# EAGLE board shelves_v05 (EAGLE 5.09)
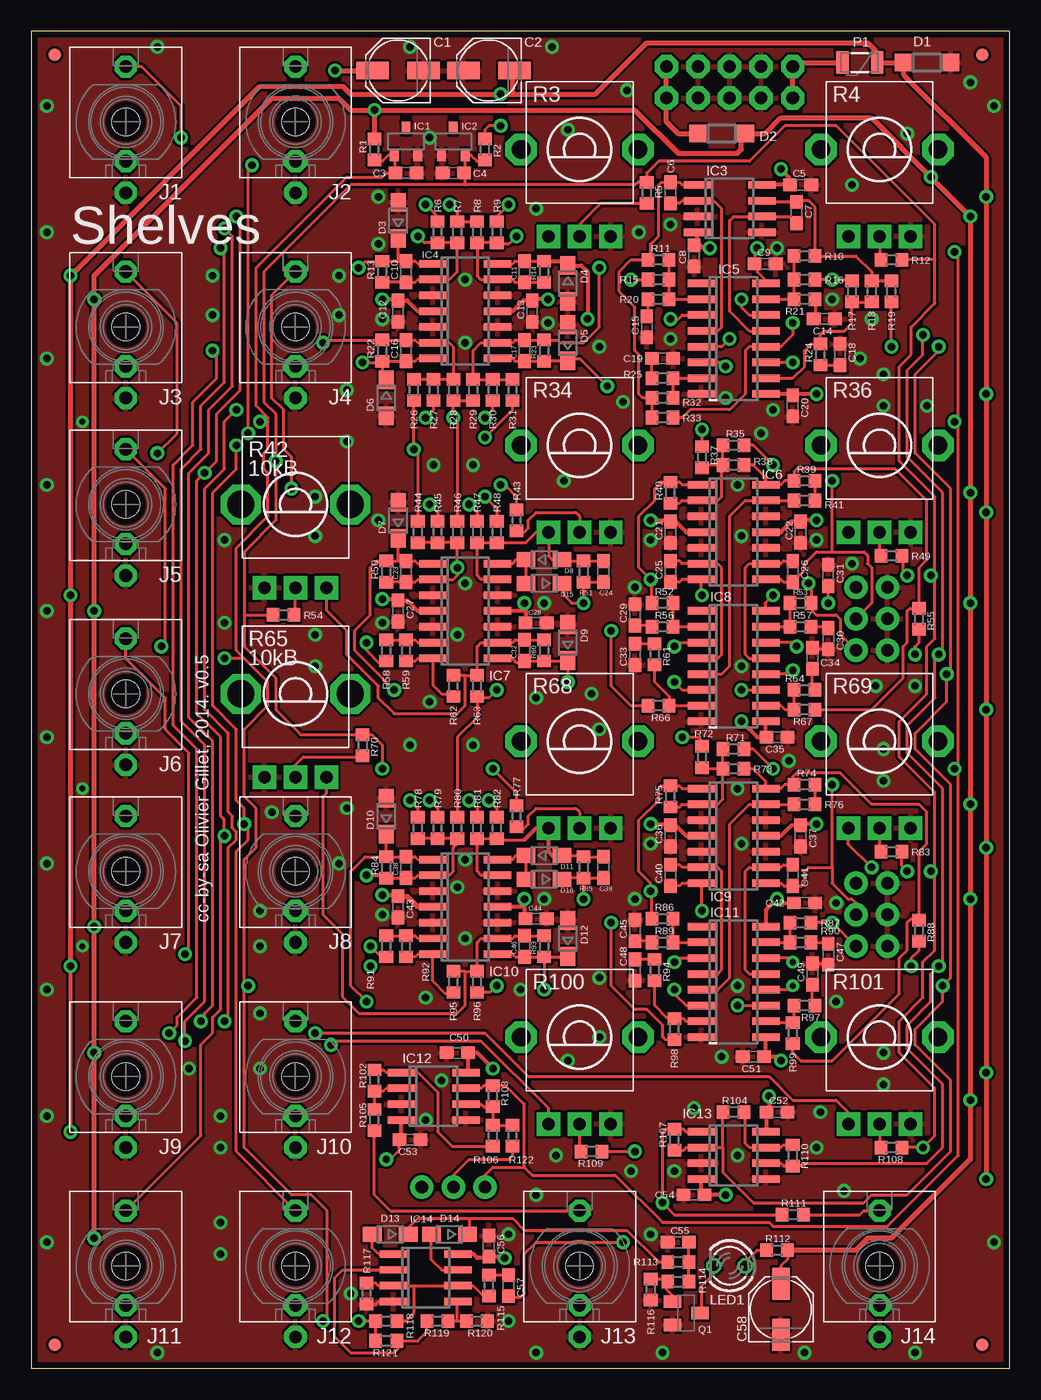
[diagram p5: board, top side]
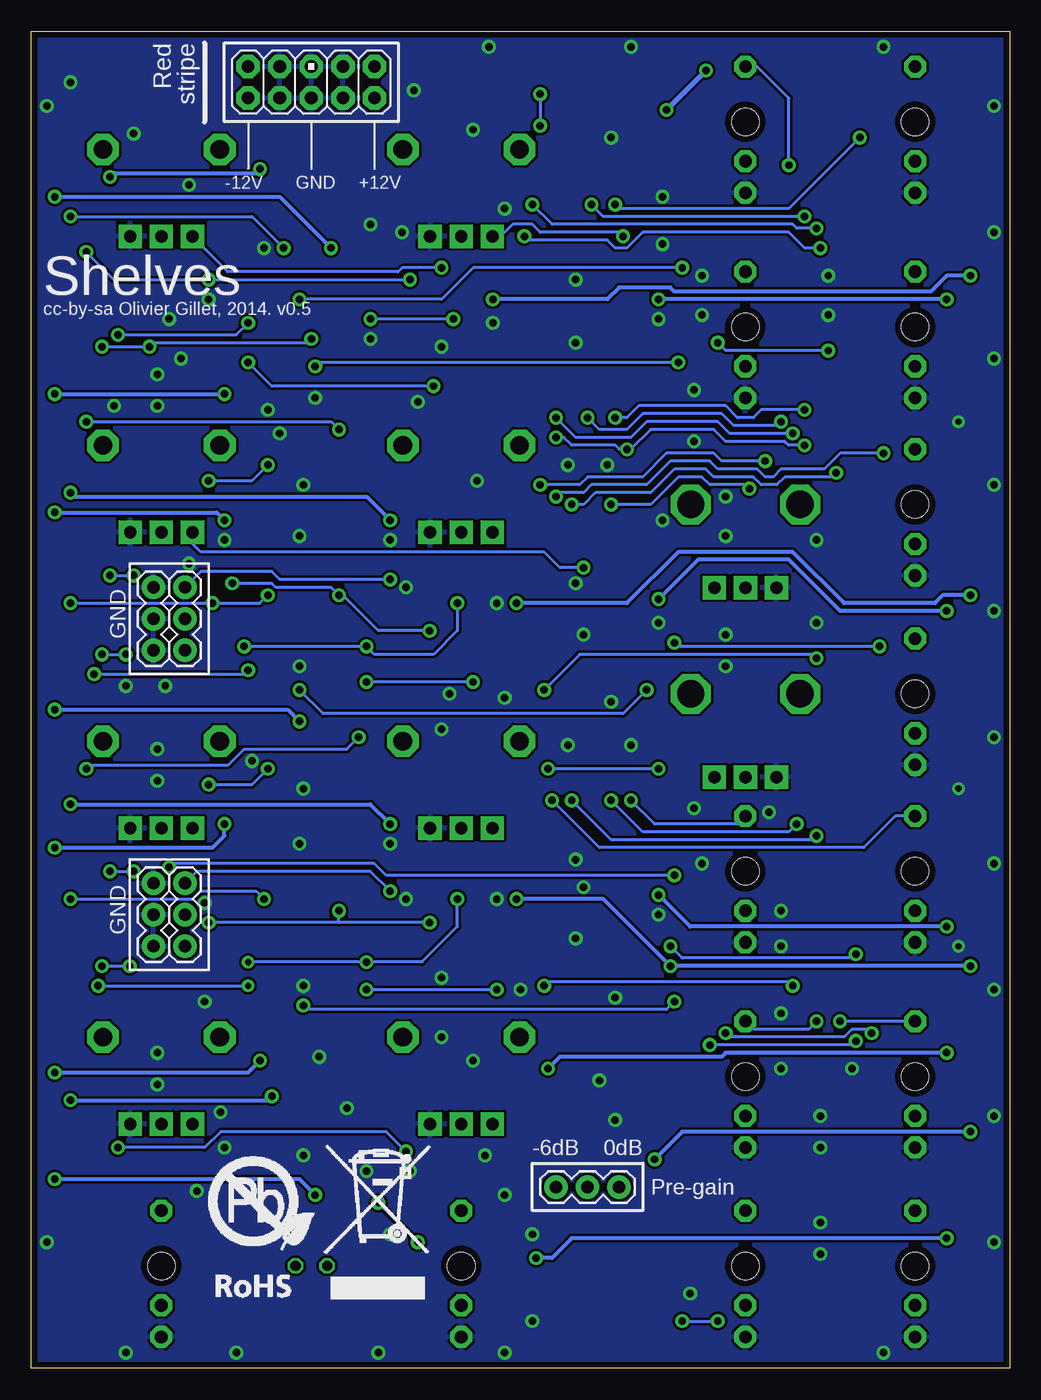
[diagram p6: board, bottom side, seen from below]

Size 78.74 x 107.63 mm. Coordinates in mm from the lower left corner, seen from the top.
Outline: 0,0 78.74,0 78.74,107.63 0,107.63 0,0
Copper layers (1*16): Top 0.035mm / dielectric 1.5mm / Bottom 0.035mm
Design rules "PCBCart-Standard": minimum track width 8mil, minimum drill 0.4mm, track to track 8mil, track to pad 8mil, pad to pad 8mil, via to via 8mil, smd to smd 8mil, copper to edge 20mil, drill to drill 8mil, minimum pad ring 8mil, minimum via ring 10mil, stop-mask expansion 3mil, vias tented up to drill 25mil, thermal gap 8mil

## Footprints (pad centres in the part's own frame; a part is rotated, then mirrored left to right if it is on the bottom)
PANASONIC_C = smd 2.6 x 1.4: + 2.05,0; - -2.05,0
C0603 = smd 1.1 x 1: 1 -0.85,0; 2 0.85,0
SOD123 = smd 1.4 x 1.4: A 1.9,0; C -1.9,0
SOD323-W = smd 1.5 x 1.2: A 1.45,0; C -1.45,0
DBZ_R-PDSO-G3 = smd 0.7 x 1: 1 -0.95,-1.1; 2 0.95,-1.1; 3 0,1.1
SO08 = smd 0.6 x 2.2: 1 -1.905,-2.6; 2 -0.635,-2.6; 3 0.635,-2.6; 4 1.905,-2.6; 5 1.905,2.6; 6 0.635,2.6; 7 -0.635,2.6; 8 -1.905,2.6
SO14 = smd 0.6 x 2.2: 1 -3.81,-2.6; 2 -2.54,-2.6; 3 -1.27,-2.6; 4 0,-2.6; 5 1.27,-2.6; 6 2.54,-2.6; 7 3.81,-2.6; 8 3.81,2.6; 9 2.54,2.6; 10 1.27,2.6; 11 0,2.6; 12 -1.27,2.6; 13 -2.54,2.6; 14 -3.81,2.6
SOIC16N = smd 0.6 x 2.2: 1 -4.445,-2.6; 2 -3.175,-2.6; 3 -1.905,-2.6; 4 -0.635,-2.6; 5 0.635,-2.6; 6 1.905,-2.6; 7 3.175,-2.6; 8 4.445,-2.6; 9 4.445,2.6; 10 3.175,2.6; 11 1.905,2.6; 12 0.635,2.6; 13 -0.635,2.6; 14 -1.905,2.6; 15 -3.175,2.6; 16 -4.445,2.6
WQP_PJ_301M6 = drill 1.016 pad 1.778 octagon: P1 0,-5.715; P2 0,-3.175; P3 0,4.445 | hole 2.2: 0,0
FIDUCIAL-1X2 = smd 1 x 1: 1 0,0
1X03 = drill 1.016 pad 1.88 round: 1 0,0; 2 2.54,0; 3 5.08,0
AVR_ICSP = drill 1.016 pad 1.88 octagon: 1 -1.27,5.08; 2 1.27,5.08; 3 -1.27,2.54; 4 1.27,2.54; 5 -1.27,0; 6 1.27,0; 7 -1.27,-2.54; 8 1.27,-2.54; 9 -1.27,-5.08; 10 1.27,-5.08
LED3MM = drill 0.813 octagon: A -1.27,0; K 1.27,0
PTC-1206 = smd 1 x 1.8: 1 -1.4,0; 2 1.4,0
SOT23-BEC = smd 1 x 1.4: B -0.95,-1.1; C 0,1.1; E 0.95,-1.1
R0603 = smd 1 x 1.1: 1 -0.85,0; 2 0.85,0
ALPS_POT_VERTICAL_PS = drill 1 pad 1.88 square: P$1 -2.5,7; P$2 0,7; P$3 2.5,7 | drill 1.5 pad 2.54 octagon: P$4 -4.7,0; P$5 4.7,0
ALPS_POT_VERTICAL = drill 1 pad 1.88 square: P$1 -2.5,6.7; P$2 0,6.7; P$3 2.5,6.7 | drill 2.2 pad 3.175 octagon: P$4 -4.4,0; P$5 4.4,0

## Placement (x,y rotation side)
C1  22u  [PANASONIC_C]  29.53,104.46 180 top
C2  22u  [PANASONIC_C]  36.83,104.46 180 top
C3  100n  [C0603]  30.16,96.2 0 top
C4  100n  [C0603]  33.97,96.2 180 top
C5  100n  [C0603]  61.91,95.25 0 top
C6  68p  [C0603]  51.44,94.61 90 top
C7  68p  [C0603]  61.59,93.03 90 top
C8  100n  [C0603]  53.34,89.53 90 top
C9  100n  [C0603]  59.05,88.9 0 top
C10  560p  [C0603]  30.16,88.27 270 top
C11  560p  [C0603]  39.69,88.27 270 top
C12  100n  [C0603]  29.53,85.09 270 top
C13  100n  [C0603]  40.32,85.09 90 top
C14  560p  [C0603]  63.82,84.45 0 top
C15  560p  [C0603]  49.53,83.82 270 top
C16  560p  [C0603]  30.16,81.92 90 top
C17  560p  [C0603]  39.69,81.92 90 top
C18  560p  [C0603]  65.09,81.6 90 top
C19  560p  [C0603]  50.8,81.28 0 top
C20  100n  [C0603]  61.28,77.47 90 top
C21  100n  [C0603]  51.44,67.31 270 top
C22  100n  [C0603]  61.91,67.31 90 top
C23  560p  [C0603]  30.16,64.14 270 top
C24  560p  [C0603]  46.04,64.14 90 top
C25  68p  [C0603]  51.44,64.14 270 top
C26  68p  [C0603]  61.28,64.14 270 top
C27  100n  [C0603]  29.53,60.96 270 top
C28  100n  [C0603]  40.64,60.01 180 top
C29  560p  [C0603]  48.58,60.64 90 top
C30  560p  [C0603]  64.14,58.74 270 top
C31  100n  [C0603]  64.14,63.82 90 top
C32  560p  [C0603]  39.69,57.78 90 top
C33  560p  [C0603]  48.58,57.47 270 top
C34  560p  [C0603]  62.87,57.15 90 top
C35  100n  [C0603]  60.01,50.8 180 top
C36  100n  [C0603]  51.44,42.86 270 top
C37  100n  [C0603]  61.91,42.86 90 top
C38  560p  [C0603]  30.16,40.32 270 top
C39  560p  [C0603]  46.04,40.32 90 top
C40  68p  [C0603]  51.44,39.69 270 top
C41  68p  [C0603]  61.28,39.69 270 top
C42  100n  [C0603]  62.23,37.47 0 top
C43  100n  [C0603]  29.53,37.15 270 top
C44  100n  [C0603]  40.64,36.2 180 top
C45  560p  [C0603]  48.58,35.24 90 top
C46  560p  [C0603]  39.69,33.97 90 top
C47  560p  [C0603]  64.14,33.34 270 top
C48  560p  [C0603]  48.58,32.07 270 top
C49  560p  [C0603]  62.87,31.75 90 top
C50  100n  [C0603]  34.29,25.4 180 top
C51  100n  [C0603]  58.1,25.08 0 top
C52  100n  [C0603]  60.01,20.64 0 top
C53  100n  [C0603]  30.48,18.41 180 top
C54  100n  [C0603]  53.34,13.97 0 top
C55  100n  [C0603]  52.07,10.16 180 top
C56  100n  [C0603]  36.83,9.84 90 top
C57  100n  [C0603]  38.42,6.67 270 top
C58  22u  [PANASONIC_C]  60.33,4.76 90 top
D1  1N5819HW  [SOD123]  72.07,105.09 180 top
D2  1N5819HW  [SOD123]  55.56,99.38 180 top
D3  1N4148  [SOD323-W]  29.53,92.39 90 top
D4  1N4148  [SOD323-W]  43.18,87.31 270 top
D5  1N4148  [SOD323-W]  43.18,82.55 90 top
D6  1N4148  [SOD323-W]  28.57,78.11 270 top
D7  1N4148  [SOD323-W]  29.53,68.26 90 top
D8  1N4148  [SOD323-W]  41.27,65.09 0 top
D9  1N4148  [SOD323-W]  43.18,58.42 90 top
D10  1N4148  [SOD323-W]  28.57,44.45 90 top
D11  1N4148  [SOD323-W]  41.27,41.27 0 top
D12  1N4148  [SOD323-W]  43.18,34.61 90 top
D13  1N4148  [SOD323-W]  28.89,10.79 180 top
D14  1N4148  [SOD323-W]  33.66,10.79 180 top
D15  1N4148  [SOD323-W]  41.27,63.18 180 top
D16  1N4148  [SOD323-W]  41.27,39.37 180 top
IC1  LM4040B10  [DBZ_R-PDSO-G3]  30.16,98.74 0 top
IC2  LM4040B10  [DBZ_R-PDSO-G3]  33.97,98.74 0 top
IC3  TL072D  [SO08]  56.2,93.34 270 top
IC4  TL074D  [SO14]  34.92,85.09 270 top
IC5  V2164SZ  [SOIC16N]  56.52,82.87 270 top
IC6  TL074D  [SO14]  56.52,67.31 270 top
IC7  TL074D  [SO14]  34.92,60.96 270 top
IC8  V2164SZ  [SOIC16N]  56.52,56.52 270 top
IC9  TL074D  [SO14]  56.52,42.86 270 top
IC10  TL074D  [SO14]  34.92,37.15 270 top
IC11  V2164SZ  [SOIC16N]  56.52,31.11 270 top
IC12  TL072D  [SO08]  32.38,21.91 270 top
IC13  TL072D  [SO08]  56.52,17.14 270 top
IC14  TL072D  [SO08]  31.75,7.3 270 top
J1  PJ301_THONKICONN6  [WQP_PJ_301M6]  7.62,100.33 0 top
J2  PJ301_THONKICONN6  [WQP_PJ_301M6]  21.27,100.33 0 top
J3  PJ301_THONKICONN6  [WQP_PJ_301M6]  7.62,83.82 0 top
J4  PJ301_THONKICONN6  [WQP_PJ_301M6]  21.27,83.82 0 top
J5  PJ301_THONKICONN6  [WQP_PJ_301M6]  7.62,69.53 0 top
J6  PJ301_THONKICONN6  [WQP_PJ_301M6]  7.62,54.29 0 top
J7  PJ301_THONKICONN6  [WQP_PJ_301M6]  7.62,40.01 0 top
J8  PJ301_THONKICONN6  [WQP_PJ_301M6]  21.27,40.01 0 top
J9  PJ301_THONKICONN6  [WQP_PJ_301M6]  7.62,23.5 0 top
J10  PJ301_THONKICONN6  [WQP_PJ_301M6]  21.27,23.5 0 top
J11  PJ301_THONKICONN6  [WQP_PJ_301M6]  7.62,8.26 0 top
J12  PJ301_THONKICONN6  [WQP_PJ_301M6]  21.27,8.26 0 top
J13  PJ301_THONKICONN6  [WQP_PJ_301M6]  44.13,8.26 0 top
J14  PJ301_THONKICONN6  [WQP_PJ_301M6]  68.26,8.26 0 top
JP1  FIDUCIAL1X2  [FIDUCIAL-1X2]  1.91,105.73 0 top
JP2  FIDUCIAL1X2  [FIDUCIAL-1X2]  76.52,105.73 0 top
JP3  FIDUCIAL1X2  [FIDUCIAL-1X2]  1.91,1.91 0 top
JP4  FIDUCIAL1X2  [FIDUCIAL-1X2]  76.52,1.91 0 top
JP5  [1X03]  66.36,57.78 90 bottom
JP6  [1X03]  68.9,57.78 90 bottom
JP7  [1X03]  68.9,33.97 90 bottom
JP11  M05X2PTH  [AVR_ICSP]  56.2,103.5 270 bottom
JP12  [1X03]  31.43,14.61 180 bottom
JP13  [1X03]  66.36,33.97 90 bottom
LED1  WP-710A10GD  [LED3MM]  56.2,8.26 180 top
P1  PTCSMD  [PTC-1206]  66.67,105.09 180 top
Q1  MMBT3904  [SOT23-BEC]  52.7,4.45 270 top
R1  3.3k  [R0603]  27.62,98.11 270 top
R2  1.0k  [R0603]  36.51,98.11 270 top
R3  10kB  [ALPS_POT_VERTICAL_PS]  44.13,98.11 180 top
R4  10kB  [ALPS_POT_VERTICAL_PS]  68.26,98.11 180 top
R5  100k  [R0603]  49.53,94.61 270 top
R6  100k  [R0603]  32.7,91.44 270 top
R7  100k  [R0603]  34.29,91.44 270 top
R8  100k  [R0603]  35.88,91.44 270 top
R9  100k  [R0603]  37.47,91.44 270 top
R10  100k  [R0603]  62.23,89.53 0 top
R11  100k  [R0603]  50.48,89.22 180 top
R12  100k  [R0603]  69.22,89.22 180 top
R13  18k  [R0603]  28.26,88.27 90 top
R14  18k  [R0603]  41.27,88.27 90 top
R15  100k  [R0603]  50.48,87.63 0 top
R16  100k  [R0603]  62.23,87.63 180 top
R17  100k  [R0603]  66.04,86.68 270 top
R18  100k  [R0603]  67.63,86.68 270 top
R19  100k  [R0603]  69.22,86.68 270 top
R20  510  [R0603]  50.48,86.04 0 top
R21  510  [R0603]  62.23,86.04 180 top
R22  12k  [R0603]  28.26,81.92 270 top
R23  12k  [R0603]  41.27,81.92 270 top
R24  510  [R0603]  63.5,81.6 90 top
R25  510  [R0603]  50.8,79.69 0 top
R26  120k  [R0603]  30.8,78.74 90 top
R27  120k  [R0603]  32.38,78.74 90 top
R28  200k  [R0603]  33.97,78.74 90 top
R29  200k  [R0603]  35.56,78.74 90 top
R30  120k  [R0603]  37.15,78.74 90 top
R31  120k  [R0603]  38.73,78.74 90 top
R32  100k  [R0603]  50.8,78.11 0 top
R33  100k  [R0603]  50.8,76.52 0 top
R34  10kB  [ALPS_POT_VERTICAL_PS]  44.13,74.3 180 top
R35  100k  [R0603]  56.52,74.3 0 top
R36  10kB  [ALPS_POT_VERTICAL_PS]  68.26,74.3 180 top
R37  100k  [R0603]  53.98,73.34 270 top
R38  100k  [R0603]  56.52,72.71 0 top
R39  100k  [R0603]  62.23,71.44 0 top
R40  100k  [R0603]  51.44,70.48 90 top
R41  100k  [R0603]  62.23,69.85 180 top
R42  10kB  [ALPS_POT_VERTICAL]  21.27,69.53 180 top
R43  100k  [R0603]  39.05,68.26 270 top
R44  120k  [R0603]  31.11,67.31 270 top
R45  120k  [R0603]  32.7,67.31 270 top
R46  200k  [R0603]  34.29,67.31 270 top
R47  100k  [R0603]  35.88,67.31 270 top
R48  100k  [R0603]  37.47,67.31 270 top
R49  100k  [R0603]  69.22,65.41 180 top
R50  12k  [R0603]  28.57,64.14 90 top
R51  18k  [R0603]  44.45,64.14 270 top
R52  100k  [R0603]  50.8,61.59 0 top
R53  100k  [R0603]  61.91,61.59 180 top
R54  200k  [R0603]  20.32,60.64 0 top
R55  100k  [R0603]  71.44,60.33 270 top
R56  510  [R0603]  50.8,59.69 0 top
R57  510  [R0603]  61.91,59.69 180 top
R58  100k  [R0603]  28.57,57.78 90 top
R59  100k  [R0603]  30.16,57.78 270 top
R60  22k  [R0603]  41.27,57.78 270 top
R61  510  [R0603]  50.16,57.47 270 top
R62  150k  [R0603]  33.97,54.93 90 top
R63  1.5M  [R0603]  35.88,54.93 90 top
R64  510  [R0603]  62.23,54.61 180 top
R65  10kB  [ALPS_POT_VERTICAL]  21.27,54.29 180 top
R66  100k  [R0603]  50.48,53.34 0 top
R67  100k  [R0603]  62.23,53.02 180 top
R68  10kB  [ALPS_POT_VERTICAL_PS]  44.13,50.48 180 top
R69  10kB  [ALPS_POT_VERTICAL_PS]  68.26,50.48 180 top
R70  200k  [R0603]  26.67,50.16 270 top
R71  100k  [R0603]  56.52,49.85 0 top
R72  100k  [R0603]  53.98,49.21 270 top
R73  100k  [R0603]  56.52,48.26 0 top
R74  100k  [R0603]  62.23,46.99 0 top
R75  100k  [R0603]  51.44,46.04 90 top
R76  100k  [R0603]  62.23,45.4 180 top
R77  100k  [R0603]  39.05,44.45 270 top
R78  120k  [R0603]  31.11,43.5 270 top
R79  120k  [R0603]  32.7,43.5 270 top
R80  200k  [R0603]  34.29,43.5 270 top
R81  100k  [R0603]  35.88,43.5 270 top
R82  100k  [R0603]  37.47,43.5 270 top
R83  100k  [R0603]  69.22,41.59 180 top
R84  12k  [R0603]  28.57,40.32 90 top
R85  18k  [R0603]  44.45,40.32 270 top
R86  100k  [R0603]  50.8,36.2 0 top
R87  100k  [R0603]  61.91,35.88 180 top
R88  100k  [R0603]  71.44,35.24 270 top
R89  510  [R0603]  50.8,34.29 0 top
R90  510  [R0603]  61.91,34.29 180 top
R91  100k  [R0603]  28.57,33.97 90 top
R92  100k  [R0603]  30.16,33.97 270 top
R93  22k  [R0603]  41.27,33.97 270 top
R94  510  [R0603]  50.16,32.07 270 top
R95  150k  [R0603]  33.97,31.11 90 top
R96  1.5M  [R0603]  35.88,31.11 90 top
R97  510  [R0603]  62.23,29.21 180 top
R98  100k  [R0603]  51.75,27.3 90 top
R99  100k  [R0603]  61.28,26.99 90 top
R100  10kB  [ALPS_POT_VERTICAL_PS]  44.13,26.67 180 top
R101  10kB  [ALPS_POT_VERTICAL_PS]  68.26,26.67 180 top
R102  100k  [R0603]  27.62,23.18 90 top
R103  100k  [R0603]  37.15,21.91 90 top
R104  100k  [R0603]  56.52,20.64 180 top
R105  100k  [R0603]  27.62,20 90 top
R106  200k  [R0603]  37.15,18.73 90 top
R107  200k  [R0603]  51.75,18.41 90 top
R108  100k  [R0603]  69.22,17.78 180 top
R109  100k  [R0603]  45.09,17.46 180 top
R110  100k  [R0603]  61.28,17.14 90 top
R111  1.0k  [R0603]  61.28,12.38 0 top
R112  1.0k  [R0603]  60.01,9.53 0 top
R113  12k  [R0603]  52.07,8.57 0 top
R114  100k  [R0603]  52.07,6.99 180 top
R115  100k  [R0603]  36.83,6.67 270 top
R116  22k  [R0603]  49.85,6.35 90 top
R117  100k  [R0603]  26.99,6.03 90 top
R118  100k  [R0603]  28.57,3.81 180 top
R119  220k  [R0603]  32.7,3.81 180 top
R120  100k  [R0603]  35.88,3.81 180 top
R121  100k  [R0603]  28.57,2.22 180 top
R122  100k  [R0603]  38.73,18.73 270 top
U$2  [ROHS_BIG]  65.72,4.76 0 bottom

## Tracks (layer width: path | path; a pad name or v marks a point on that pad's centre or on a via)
AREF_+10  (via drill 0.6)
  Top 0.254: C3.1 29.31,97.54 IC1.1 28.75,97.64 28.26,97.16 27.73,97.16 R1.2 | C3.1 29.21,96.1 | 19.05,76.2 19.05,76.52 18.1,77.47 18.1,88.58 25.4,95.89 28.26,95.89 28.57,96.2 C3.1 | 17.14,57.15 19.05,55.24 19.05,53.34 17.14,51.44 17.14,46.04 18.1,45.09 18.1,41.91 17.14,40.96 17.14,30.8 | 17.14,57.15 16.51,57.78 16.51,66.04 19.05,68.58 19.05,72.07 18.73,72.39 18.73,73.66 19.05,73.98 19.05,76.2 | R29.1 R28.1 v33.97,76.52 34.29,76.2 R46.1 | 19.05,76.2 v18.41,76.2 | 17.14,57.15 v15.56,57.15 | R121.2 R118.2 v26.35,3.81 | v23.5,3.81 23.81,4.13 23.81,12.7 22.54,13.97 20.95,13.97 17.14,17.78 17.14,30.8 | 17.14,30.8 v17.46,30.8 | R80.1 34.29,50.8 35.88,52.39 R63.1 35.98,53.98 36.83,53.98 v37.47,54.61 | v37.47,30.8 36.93,30.27 R96.1
  Bottom 0.254: v33.97,76.52 33.02,75.56 30.8,75.56 29.53,76.83 23.18,76.83 22.23,75.88 18.73,75.88 v18.41,76.2 | v15.56,57.15 15.88,57.47 34.61,57.47 v37.47,54.61 | v26.35,3.81 v23.5,3.81 | v17.46,30.8 17.78,31.11 37.15,31.11 v37.47,30.8
AREF_-10  (via drill 0.6)
  Top 0.254: R108.1 v71.75,17.78 72.71,18.73 72.71,22.54 69.85,25.4 69.85,27.94 71.75,29.84 71.75,32.7 72.71,33.66 72.71,40.01 | 72.71,40.01 72.71,46.35 69.85,49.21 69.85,52.07 72.07,54.29 72.07,58.1 72.71,58.74 72.71,63.82 | 72.71,63.82 72.71,70.17 69.85,73.03 69.85,80.64 70.8,81.6 70.8,83.82 72.71,85.72 72.71,89.22 | 72.71,89.22 72.71,92.08 64.77,100.01 60.64,100.01 57.78,97.16 50.48,97.16 49.53,96.2 R5.1 48.79,95.47 48.58,95.25 34.92,95.25 | 72.71,89.22 R12.1 | R49.1 70.17,65.3 70.17,64.14 v70.48,63.82 | 72.71,63.82 v72.39,63.82 | 70.17,41.49 R83.1 70.06,40.42 v70.48,40.01 | 72.71,40.01 v72.39,40.01 | 17.14,60.64 17.14,58.1 19.68,55.56 19.68,53.02 21.69,51.02 R70.1 | 17.14,60.64 17.14,65.72 19.68,68.26 v19.68,73.03 19.68,76.83 18.73,77.79 18.73,88.27 25.72,95.25 34.92,95.25 | 17.14,60.64 R54.1 | R70.1 26.57,51.12 | v28.26,48.26 28.26,50.16 27.41,51.02 R70.1 | R109.1 v48.58,17.46 | R2.2 36.41,97.16 35.88,97.16 35.39,97.64 IC2.2 34.92,96.3 C4.1 34.92,96.1 34.92,95.25 | R77.1 39.05,46.35 v37.15,48.26 | v37.78,71.12 38.1,71.12 39.05,70.17 R43.1
  Bottom 0.254: v72.39,63.82 v70.48,63.82 | v72.39,40.01 v70.48,40.01 | v37.78,71.12 34.61,71.12 33.97,71.75 29.53,71.75 27.62,73.66 23.81,73.66 23.18,73.03 v19.68,73.03 | v28.26,48.26 v37.15,48.26 | v48.58,17.46 50.16,19.05 63.5,19.05 64.77,17.78 v71.75,17.78
BP_1  (via drill 0.6)
  Top 0.254: v53.98,36.83 53.98,38.99 IC9.7 52.39,39.05 52.17,38.84 C40.2 | R87.1 v64.45,35.88 JP13.1 | R98.1 51.02,26.45 50.8,26.67 50.8,27.62 49.53,28.89 48.58,28.89 46.67,30.8 v46.67,35.88
  Bottom 0.254: 53.98,35.88 v64.45,35.88 | v46.67,35.88 53.98,35.88 | 53.98,35.88 v53.98,36.83
BP_2  (via drill 0.6)
  Top 0.254: C25.2 52.17,63.28 52.39,63.5 IC6.7 53.91,62.29 v53.98,62.23 | R66.1 48.26,53.34 46.67,54.93 v46.67,59.37 | v62.55,63.18 62.76,62.97 R53.1 62.87,61.49 62.87,60.96 63.18,60.64 64.77,60.64 65.09,60.33 65.09,59.05 JP5.1
  Bottom 0.254: v46.67,59.37 50.8,59.37 53.66,62.23 v53.98,62.23 54.61,62.87 59.05,62.87 59.37,63.18 v62.55,63.18
F_GLOBAL  (via drill 0.6)
  Top 0.254: R8.1 R7.1 34.29,93.03 v33.66,93.66 | v16.51,92.71 16.83,92.39 16.83,78.74 14.92,76.83 14.92,73.03 v13.97,72.07 13.34,71.44 13.34,52.7 15.24,50.8 15.24,44.45 15.56,44.13 v15.56,42.86 15.24,42.55 15.24,28.89 14.61,28.26 14.61,26.99 13.65,26.04 13.65,18.73 J11.P3 | v35.24,69.53 35.88,68.9 R47.1 | v35.24,45.72 35.88,45.09 R81.1
  Bottom 0.254: v33.66,93.66 32.7,92.71 v16.51,92.71 | v13.97,72.07 14.29,71.75 18.1,71.75 18.73,71.12 20,71.12 20.64,71.75 23.81,71.75 24.45,72.39 26.99,72.39 28.89,70.48 33.34,70.48 34.29,69.53 v35.24,69.53 | v35.24,45.72 32.07,42.55 15.88,42.55 v15.56,42.86
GAIN_GLOBAL  (via drill 0.6)
  Top 0.254: J12.P3 16.51,17.46 16.51,41.59 17.46,42.55 17.46,43.5 v17.14,43.81 17.14,45.09 16.51,45.72 16.51,51.44 14.61,53.34 14.61,70.48 16.51,72.39 v16.51,74.3 | R31.1 38.73,77.15 v36.51,74.93 | R26.1 v30.8,73.98 31.11,73.66 R44.1 | v32.07,45.72 32.7,45.09 R79.1
  Bottom 0.254: v16.51,74.3 17.78,74.3 18.1,74.61 22.86,74.61 23.81,75.56 28.89,75.56 30.48,73.98 v30.8,73.98 31.43,73.98 31.75,74.3 35.24,74.3 35.88,74.93 v36.51,74.93 | v32.07,45.72 29.53,43.18 17.78,43.18 v17.14,43.81
GND  (via drill 0.5, 0.6)
  Top 0.254: C47.2 64.02,32.6 C49.2 | IC14.4 27.94,5.4 27.73,5.18 R117.1 | C34.2 62.98,57.89 C30.2
  other vias: 60.01,90.17 64.45,86.04 51.44,92.08 51.44,82.87 49.85,66.67 56.83,71.12 63.18,66.67 59.69,77.15 55.88,78.11 49.85,42.23 60.96,48.9 56.83,46.67 48.58,62.87 48.58,37.78 64.77,29.53 51.75,15.88 63.5,20.64 56.83,17.14 66.67,81.28 32.07,99.06 28.26,84.45 41.59,84.14 34.92,82.55 27.94,94.3 45.72,82.23 67.63,84.45 47.62,77.79 25.4,74.61 25.4,78.74 22.86,70.17 28.26,60.01 55.56,25.08 71.12,54.93 68.58,49.85 45.09,54.29 34.92,63.18 34.29,59.05 34.92,87.63 28.26,36.51 31.75,20 33.02,23.18 48.9,91.44 40.64,93.34 14.61,87.95 14.61,84.77 24.77,84.77 27.94,68.26 15.56,66.67 15.56,60.01 22.86,59.05 22.86,56.52 25.4,45.09 19.37,44.77 18.41,36.83 30.48,50.16 18.41,28.57 43.18,24.77 12.7,24.13 39.37,30.48 45.72,26.67 45.72,31.43 56.83,30.8 57.15,42.23 45.72,51.44 57.15,66.99 57.15,56.52 32.38,72.71 35.56,72.71 42.86,71.44 43.18,99.69 47.94,102.87 72.07,77.47 70.48,99.38 63.18,17.78 42.23,17.14 40.64,13.97 15.24,17.78 15.24,20.32 18.41,24.13 25.72,6.03 38.42,10.79 38.42,3.81 15.24,9.21 35.56,50.16 40.64,53.98 27.94,90.49 31.75,29.84 34.92,40.96 48.26,15.88 18.41,33.97 34.29,38.73 34.92,34.61 68.58,77.47 68.58,80.01 58.74,75.25 68.58,22.86 68.58,25.4 65.41,14.29 75.56,103.5 32.07,53.66 4.13,76.2 4.13,46.67 4.13,33.97 68.58,47.31 24.77,87.95 22.86,66.99 24.77,40.64 15.24,11.75 53.34,20.95 1.27,91.44 1.27,101.6 1.27,81.28 1.27,71.12 1.27,60.96 1.27,50.8 1.27,40.64 10.16,1.27 40.64,1.27 50.8,1.27 62.23,1.27 71.12,1.27 77.47,10.16 10.16,106.36 49.85,10.79 66.04,95.25 1.27,30.48 1.27,20.32 1.27,10.16 77.47,101.6 30.48,106.36 41.91,106.36 64.77,37.47 66.04,64.77 67.94,54.93 41.27,37.78 41.27,61.59
  pour Bottom: 0,107.63 0,0 78.74,0 78.74,107.63
  pour Top (isolate 0.203): 0,107.63 0,0 78.74,0 78.74,107.63
HP_1  (via drill 0.6)
  Top 0.254: IC9.1 52.39,46.67 52.17,46.89 R75.2 50.7,46.89 50.48,46.67 50.48,45.72 48.9,44.13 48.9,40.01 49.85,39.05 v49.85,38.42 49.95,38.31 R86.1
  Bottom 0.254: JP13.3 65.41,40.01 51.44,40.01 v49.85,38.42
HP_2  (via drill 0.6)
  Top 0.254: IC6.1 52.39,71.12 52.17,71.33 R40.2 | R40.2 51.02,71.33 | R40.2 50.7,71.33 50.16,70.8 50.16,69.85 48.9,68.58 48.9,64.45 v49.85,63.5 49.95,63.4 R52.1
  Bottom 0.254: JP5.3 65.09,64.14 59.37,64.14 58.74,63.5 v49.85,63.5
IN  (via drill 0.6)
  Top 0.254: v48.26,87.63 R15.1 | R16.1 v64.45,87.63 65.94,87.63 R17.1 | IC12.7 36.2,22.54 36.41,22.76 R103.2 | R103.2 37.25,22.86 | 74.61,48.26 74.61,17.14 68.9,11.43 59.69,11.43 59.37,11.75 50.8,11.75 46.99,15.56 40.32,15.56 39.69,16.19 | 74.61,48.26 v74.3,48.26 | 74.61,48.26 74.61,76.2 | 74.61,76.2 v74.3,76.2 | 74.61,76.2 74.61,89.53 v74.3,89.85 | 53.87,74.3 R37.1 v53.98,75.56 | 53.76,49.85 R72.1 53.98,50.48 53.66,50.8 v52.39,50.8 | R103.2 38.2,22.76 39.69,21.27 39.69,16.19 | 39.69,16.19 37.15,16.19 36.51,15.56 JP12.3
  Bottom 0.254: v48.26,87.63 v64.45,87.63 72.07,87.63 v74.3,89.85 | v53.98,75.56 54.61,76.2 v74.3,76.2 | v52.39,50.8 53.34,49.85 61.59,49.85 62.87,48.58 73.98,48.58 v74.3,48.26
IN_INV
  Top 0.254: R102.2 28.36,24.03 28.57,23.81 IC12.1 31.11,23.81 32.7,22.23 32.7,19.05 33.87,17.88 R106.1
IN_INV1
  Top 0.254: R104.1 57.47,20.54 57.47,18.1 57.78,17.78 IC13.7 60.33,17.78 60.54,18 R110.2
J_HF_CV  (via drill 0.6)
  Top 0.254: v17.78,96.84 17.46,96.52 v17.46,75.25 | R30.1 37.15,77.15 v36.51,76.52
  Bottom 0.254: J2.P3 20.32,104.78 17.78,102.23 v17.78,96.84 | v36.51,76.52 34.92,74.93 30.48,74.93 29.21,76.2 23.5,76.2 22.54,75.25 v17.46,75.25
J_HF_F  (via drill 0.6)
  Top 0.254: v31.75,93.66 32.7,92.71 R6.1 | v12.06,99.06 12.06,101.6 8.89,104.78 J1.P3
  Bottom 0.254: v31.75,93.66 31.43,93.34 17.78,93.34 v12.06,99.06
J_IN
  Top 0.254: R105.1 27.62,13.97 28.89,12.7 J13.P3
J_LF_CV  (via drill 0.6)
  Top 0.254: v15.56,27.94 15.88,28.26 15.88,41.91 16.51,42.55 16.51,43.18 16.19,43.5 16.19,44.45 15.88,44.77 15.88,51.12 13.97,53.02 13.97,70.8 15.56,72.39 15.56,76.2 v16.51,77.15 | v31.75,76.52 32.38,77.15 R27.1
  Bottom 0.254: v15.56,27.94 16.19,27.3 20.64,27.3 J10.P3 | v16.51,77.15 20,77.15 20.64,76.52 21.91,76.52 22.86,77.47 29.84,77.47 30.8,76.52 v31.75,76.52
J_LF_F  (via drill 0.6)
  Top 0.254: v15.56,91.76 16.19,91.12 16.19,79.06 14.29,77.15 14.29,73.66 12.7,72.07 12.7,52.39 14.61,50.48 14.61,29.21 13.97,28.57 13.97,28.26 v13.65,27.94 | v38.42,93.66 37.47,92.71 R9.1
  Bottom 0.254: v38.42,93.66 36.83,92.08 17.46,92.08 17.14,91.76 v15.56,91.76 | J9.P3 v13.65,27.94
LP
  Top 0.254: IC3.1 53.49,95.15 53.34,95.3 53.29,95.25 52.39,95.25 52.17,95.47 C6.2 50.7,95.47 50.48,95.25 50.48,91.12 49.85,90.49 49.85,89.43 R11.2 48.26,89.22 47.31,88.27 47.31,86.68 48.58,85.41 48.58,81.92 48.9,81.6 48.9,78.42 49.21,78.11 R32.1 R33.1
LP1
  Top 0.254: IC3.7 58.9,93.88 C7.2 61.7,93.98 62.55,93.98 63.08,93.45 R10.2 66.36,89.53 67.63,88.27 R18.1 R19.1
MID1_F1  (via drill 0.6)
  Top 0.254: IC8.14 61.28,58.42 v61.59,58.1 | v51.75,58.1 52.07,58.42 IC8.3 | D15.C 42.86,63.05 42.86,62.23 43.5,61.59 v44.45,61.59 R51.2 C24.1
  Bottom 0.254: v61.59,58.1 v51.75,58.1 51.12,57.47 46.35,57.47 44.45,59.37 v44.45,61.59
MID1_F2  (via drill 0.5, 0.6)
  Top 0.254: IC11.3 52.07,33.02 v51.75,32.7 | IC11.14 60.96,33.02 v61.28,32.7 | R85.2 C39.1 | D16.C 42.83,39.47 R85.2 | v44.45,37.78 R85.2
  Bottom 0.254: v44.45,37.78 44.45,35.56 47.31,32.7 v51.75,32.7 v61.28,32.7
MINUS_BUS  (via drill 0.5, 0.6)
  Top 0.254: v73.03,82.23 73.03,81.92 71.12,80.01 71.12,73.66 73.98,70.8 73.98,56.2 v73.66,55.88 73.66,53.66 71.12,51.12 71.12,49.85 73.98,46.99 73.98,31.43 v73.34,30.8 73.34,29.53 71.12,27.3 71.12,26.04 73.98,23.18 73.98,17.46 70.48,13.97 67.63,13.97 66.99,13.34 58.1,13.34 55.66,15.77 55.66,17.78 | R19.2 69.32,85.72 69.22,85.62 v69.22,82.23 | IC8.12 60.96,55.88 v61.28,56.2 | v61.28,30.8 60.96,30.48 IC11.12 | R107.1 52.49,17.57 52.7,17.78 IC13.2 55.66,17.78 | 55.66,17.78 R104.2 | v56.2,82.87 55.56,82.23 IC5.5
  Bottom 0.254: v73.03,82.23 v69.22,82.23 68.9,82.55 56.52,82.55 v56.2,82.87 | v73.66,55.88 61.59,55.88 v61.28,56.2 | v73.34,30.8 v61.28,30.8
N$1
  Top 0.254: IC5.2 R20.2 R15.2 R11.1
N$2
  Top 0.254: R25.1 C19.1
N$3  (via drill 0.6)
  Top 0.254: IC4.14 38.73,88.9 38.95,89.11 C11.1 R14.2 41.49,88.9 | IC5.3 52.39,84.77 52.07,84.45 v51.44,84.45
  Top 0.305: R14.2 42.83,89.11 D4.C 44.27,88.76 44.77,88.27 v44.77,84.45
  Bottom 0.254: v44.77,84.45 v51.44,84.45
N$4
  Top 0.254: IC5.4 55.24,83.5 55.56,83.82 55.56,93.34 54.93,93.98 IC3.2 52.39,93.98 52.17,93.77 C6.1
N$5
  Top 0.254: C14.1 63.08,84.57 R21.1
N$6
  Top 0.254: R122.2 38.73,17.14 38.42,16.83 35.24,16.83 33.97,15.56 JP12.2
N$7  (via drill 0.6)
  Top 0.254: IC5.6 55.56,80.96 v55.88,80.64 | IC4.7 31.11,81.28 30.9,81.06 C16.1 R22.2 | R22.2 28.16,80.96 v26.67,80.96 | D6.C 28.26,79.87 R22.2
  Bottom 0.254: v26.67,80.96 55.56,80.96 v55.88,80.64
N$8
  Top 0.254: IC10.14 38.73,40.96 39.05,41.27 D11.C D16.A
N$9
  Top 0.254: IC12.2 28.57,22.54 28.36,22.33 R102.1 R105.2
N$10
  Top 0.254: C15.1 49.63,84.77 R20.1
N$11
  Top 0.254: R95.1 33.87,30.16 33.34,30.16 32.33,31.18 IC10.7 31.11,33.34 30.9,33.12 R92.2
N$12
  Top 0.254: R109.2 44.13,17.57 R100.P$2
N$13  (via drill 0.6)
  Top 0.254: R22.1 C16.2 30.9,82.77 31.11,82.55 IC4.6 33.66,82.55 33.97,82.23 R28.2 R27.2 R26.2 | R22.1 28.16,82.87 | v14.61,81.92 14.92,81.6 14.92,79.69 13.02,77.79 13.02,74.3 11.43,72.71 11.43,51.75 13.34,49.85 13.34,29.84 11.75,28.26 11.75,27.62 v11.11,26.99 | v23.5,82.55 23.71,82.77 R22.1 | R101.P$3 65.76,20.6 64.77,21.59 61.28,21.59 59.37,23.5 40.01,23.5 36.51,26.99 v22.86,26.99
  Bottom 0.254: v23.5,82.55 22.86,81.92 v14.61,81.92 | v11.11,26.99 11.43,27.3 12.7,27.3 13.34,26.67 22.54,26.67 v22.86,26.99
N$14
  Top 0.254: IC7.14 38.73,64.77 39.05,65.09 D8.C D15.A
N$15
  Top 0.254: R108.2 68.26,17.88 R101.P$2
N$16
  Top 0.254: 59.05,86.04 IC5.15 R21.2 R16.2 R10.1
N$17
  Top 0.254: R32.2 R25.2 IC5.7
N$18  (via drill 0.6)
  Top 0.254: R14.1 C11.2 38.95,87.42 38.73,87.63 IC4.13 36.2,87.63 35.88,87.95 R8.2 R9.2 37.57,90.49 38.42,90.49 v39.05,91.12 | v15.24,90.17 15.56,89.85 15.56,79.38 13.65,77.47 13.65,73.98 12.06,72.39 12.06,52.07 13.97,50.16 13.97,29.53 12.38,27.94 v12.38,26.35 | R100.P$3 41.59,19.71 41.59,20.95 36.2,26.35 24.45,26.35 v24.13,26.04
  Bottom 0.254: v15.24,90.17 16.51,90.17 17.78,91.44 29.53,91.44 30.8,90.17 31.75,90.17 32.38,90.81 38.73,90.81 v39.05,91.12 | v12.38,26.35 12.7,26.04 v24.13,26.04
N$19
  Top 0.254: C7.1 61.06,92.71 IC3.6 56.52,92.71 56.2,92.39 56.2,85.09 57.78,83.5 IC5.13
N$21
  Top 0.254: R3.P$2 44.13,92.08 45.82,93.77 R5.2
N$22  (via drill 0.6)
  Top 0.254: v61.28,80.96 IC5.11 | IC4.8 38.73,81.28 38.95,81.06 C17.1 R23.2 41.31,81.1 D5.C 43.36,81.28 44.13,81.28 v46.35,79.06
  Bottom 0.254: v61.28,80.96 59.37,79.06 v46.35,79.06
N$23  (via drill 0.6)
  Top 0.254: v45.72,88.58 45.72,83.82 44.45,82.55 42.55,82.55 42.33,82.77 R23.1 C17.2 38.95,82.77 38.73,82.55 IC4.9 36.2,82.55 35.56,81.92 R29.2 R30.2 R31.2
  Bottom 0.254: R4.P$3 62.92,88.27 49.21,88.27 48.9,88.58 v45.72,88.58
N$25
  Top 0.254: R89.1 49.85,34.39 C45.1
N$26
  Top 0.254: R12.2 68.26,89.32 R4.P$2
N$27  (via drill 0.6)
  Top 0.254: R13.1 C10.2 30.9,87.42 31.11,87.63 IC4.2 33.66,87.63 34.29,88.27 R7.2 R6.2 31.65,90.59 v31.11,91.12
  Bottom 0.254: 41.62,91.12 R3.P$3 40.97,91.11 40.01,92.08 38.42,92.08 37.78,91.44 31.43,91.44 v31.11,91.12
N$28
  Top 0.254: R24.1 C18.1
N$29
  Top 0.254: IC5.10 61.28,79.69 62.23,80.64 62.23,81.92 62.76,82.45 R24.2 63.5,83.19 63.82,83.5 65.41,83.5 66.04,84.14 R17.2 R18.2
N$30
  Top 0.254: IC12.6 36.2,21.27 36.41,21.06 R103.1 R106.2 R122.1
N$31  (via drill 0.6)
  Top 0.254: 29.53,89.11 C10.1 30.9,89.11 31.11,88.9 IC4.1 | 29.53,89.11 R13.2 28.22,89.08 26.85,89.08 v26.35,88.58 | IC5.14 57.78,84.77 57.15,85.41 v57.15,86.04 | 29.53,89.11 D3.C
  Bottom 0.254: v26.35,88.58 43.18,88.58 45.72,86.04 v57.15,86.04
N$32  (via drill 0.6)
  Top 0.254: v36.83,45.72 37.47,45.09 R82.1
  Bottom 0.254: v36.83,45.72 33.02,41.91 11.75,41.91 9.21,44.45 J7.P3
N$33
  Top 0.254: R77.2 39.16,43.5 39.69,43.5 40.01,43.81 40.01,44.45 40.64,45.09 43.81,45.09 44.13,44.77 R68.P$2
N$34  (via drill 0.6)
  Top 0.254: IC10.1 31.11,40.96 30.9,41.17 C38.1 R84.2 | v56.83,29.21 IC11.11 | v26.99,29.53 25.72,30.8 25.72,40.01 26.89,41.17 R84.2 | R84.2 D10.C
  Bottom 0.254: v56.83,29.21 56.52,28.89 27.62,28.89 v26.99,29.53
N$35  (via drill 0.6)
  Top 0.254: R78.2 R79.2 R80.2 34.29,42.23 33.97,41.91 33.97,40.01 33.66,39.69 IC10.2 31.11,39.69 30.9,39.47 C38.2 R84.1 28.36,39.69 v26.99,39.69 | 65.72,43.44 R69.P$3 65.76,42.19 v67.63,40.32
  Bottom 0.254: v26.99,39.69 50.16,39.69 51.12,40.64 67.31,40.64 v67.63,40.32
N$36  (via drill 0.6)
  Top 0.254: R78.1 31.01,44.45 31.11,44.55 31.11,45.09 v30.48,45.72
  Bottom 0.254: v30.48,45.72 28.57,43.81 21.91,43.81 J8.P3
N$37
  Top 0.254: R83.2 68.26,41.7 R69.P$2
N$38
  Top 0.254: IC10.13 36.2,39.69 35.88,40.01 R81.2 R82.2 37.57,42.55 39.69,42.55 | C39.2 R85.1 44.35,41.27 D11.A
  Top 0.305: 39.69,42.55 40.62,43.48 R68.P$3 41.59,43.44 41.59,41.59 41.91,41.27 D11.A
N$39
  Top 0.254: R97.1 62.87,29.43 C49.1
N$40
  Top 0.254: IC11.10 59.22,27.84 R99.2 61.38,27.94 R97.2
N$41
  Top 0.254: R73.1 55.66,45.82 55.24,45.4 IC9.2 52.39,45.4 52.17,45.19 R75.1 | R73.1 R71.1 | R72.2 54.08,48.26 R73.1
N$43
  Top 0.254: IC11.2 R89.2 R86.2
N$44
  Top 0.254: C40.1 52.17,40.54 52.39,40.32 IC9.6 55.24,40.32 55.56,40.01 55.56,32.07 55.24,31.75 IC11.4
N$45
  Top 0.254: C47.1 64.03,34.29 R90.1
N$47
  Top 0.254: R56.1 49.85,59.79 C29.1
N$48
  Top 0.254: R87.2 R90.2 IC11.15
N$49
  Top 0.254: C41.1 60.54,40.54 60.33,40.32 IC9.9 57.78,40.32 57.47,40.01 57.47,32.07 57.78,31.75 IC11.13
N$50  (via drill 0.6)
  Top 0.254: R71.2 58.1,49.85 v59.69,48.26 | 59.05,38.99 IC9.8 60.33,39.05 60.54,38.84 C41.2 62.02,38.84 62.23,39.05 62.23,40.01 62.55,40.32 64.45,40.32 | JP13.2 66.36,37.47 66.04,37.78 65.72,37.78 64.45,39.05 64.45,40.32 | 64.45,40.32 v64.45,46.99
  Bottom 0.254: v59.69,48.26 60.96,46.99 v64.45,46.99
N$51
  Top 0.254: R94.1 C48.1
N$52
  Top 0.254: IC11.7 52.7,27.94 52.49,28.16 R98.2 51.65,28.26 51.12,28.26 50.16,29.21 R94.2
N$53
  Top 0.254: R76.2 IC9.13 57.78,45.4 56.2,43.81 56.2,31.43 55.24,30.48 IC11.5
N$54
  Top 0.254: R76.1 R74.2
N$55
  Top 0.254: R73.2 58.1,48.26 59.12,47.25 IC9.14 60.33,46.67 60.64,46.99 R74.1 61.28,47.09 61.28,47.62 61.59,47.94 65.09,47.94 67.63,45.4 71.44,45.4 72.07,44.77 72.07,42.23 71.44,41.59 R88.1 71.33,36.2 70.8,36.2 70.48,35.88 70.48,33.66 69.85,33.02 69.85,30.16 64.45,24.77 61.91,24.77 61.28,25.4 R99.1
N$56
  Top 0.406: JP11.1 JP11.2 51.12,100.33 52.07,99.38 D2.A
N$57  (via drill 0.6)
  Top 0.254: IC11.6 52.7,29.21 51.75,30.16 v51.75,30.48 | R93.2 v41.27,30.48 | IC10.8 38.73,33.34 38.95,33.12 C46.1 R93.2 | D12.C 43.15,33.12 R93.2
  Bottom 0.254: v41.27,30.48 v51.75,30.48
N$58
  Top 0.254: R93.1 C46.2 38.95,34.82 38.73,34.61 IC10.9 36.2,34.61 35.88,34.29 R96.2 34.92,31.96 | R65.P$1 23.77,46.31 23.5,46.04 23.5,36.51 25.08,34.92 25.08,29.84 26.35,28.57 34.29,28.57 34.92,29.21 34.92,31.96 | 34.92,31.96 R95.2
N$59
  Top 0.254: R70.2 26.57,49.21 21.91,49.21 21.27,48.58 R65.P$2
N$60
  Top 0.254: Q1.C 53.98,4.62 53.98,6.67 54.93,7.62 LED1.K
N$61
  Top 0.254: IC7.7 31.11,57.15 30.9,56.94 R59.2 | IC7.7 32.38,57.09 | R62.1 33.76,54.29 33.02,54.29 32.33,54.99 IC7.7
N$62  (via drill 0.6)
  Top 0.254: J6.P3 7.62,57.15 10.79,53.98 10.79,51.44 12.7,49.53 12.7,33.66 v12.38,33.34 | v27.3,33.97 28.16,33.12 R91.1
  Bottom 0.254: v12.38,33.34 12.7,33.02 26.35,33.02 v27.3,33.97
N$63  (via drill 0.6)
  Top 0.254: J3.P3 11.75,84.14 11.75,75.25 v10.16,73.66 | v36.51,70.17 37.47,69.22 R48.1
  Bottom 0.254: v10.16,73.66 13.65,73.66 14.92,72.39 18.41,72.39 19.05,71.75 19.68,71.75 20.32,72.39 23.5,72.39 24.13,73.03 27.3,73.03 29.21,71.12 33.66,71.12 34.29,70.48 36.2,70.48 v36.51,70.17
N$64
  Top 0.406: JP11.10 JP11.9 60.96,105.09 P1.2
N$65
  Top 0.254: R43.2 39.16,67.31 39.69,67.31 40.01,67.63 40.01,68.26 40.64,68.9 43.81,68.9 44.13,68.58 R34.P$2
N$66  (via drill 0.6)
  Top 0.254: v57.15,54.61 IC8.11 | 29.53,64.98 R50.2 27.84,64.98 27.3,64.45 27.3,60.64 26.04,59.37 26.04,57.78 v29.21,54.61 | 29.53,64.98 C23.1 30.9,64.98 31.11,64.77 IC7.1 | 29.53,64.98 D7.C
  Bottom 0.254: v57.15,54.61 55.24,52.7 31.11,52.7 v29.21,54.61
N$67  (via drill 0.6)
  Top 0.254: R50.1 C23.2 30.9,63.28 31.11,63.5 IC7.2 33.97,63.5 34.29,63.82 v34.29,64.45 R46.2 R45.2 R44.2
  Bottom 0.254: R36.P$3 65.72,67.25 65.72,66.36 65.09,65.72 37.47,65.72 36.2,64.45 v34.29,64.45
N$68  (via drill 0.6)
  Top 0.254: J4.P3 19.37,86.36 19.37,78.11 20.32,77.15 20.32,73.98 20.95,73.34 v20.95,70.8 | v32.07,69.53 32.7,68.9 R45.1
  Bottom 0.254: v20.95,70.8 21.27,71.12 24.13,71.12 24.77,71.75 26.67,71.75 28.89,69.53 v32.07,69.53
N$69
  Top 0.254: R49.2 68.26,65.51 R36.P$2
N$70
  Top 0.254: IC7.13 36.2,63.5 35.88,63.82 R47.2 R48.2 39.79,66.46 40.62,67.3 R34.P$3 | R34.P$3 41.62,67.31 | C24.2 R51.1 42.83,64.98 D8.A 41.91,65.09 41.63,65.36 R34.P$3
N$71
  Top 0.254: R64.1 62.87,54.83 C34.1
N$72
  Top 0.254: IC8.10 60.33,53.34 60.64,53.02 R67.2 R64.2
N$73
  Top 0.254: R38.1 55.56,72.61 55.56,70.17 55.24,69.85 IC6.2 52.39,69.85 52.17,69.64 R40.1 | R38.1 R35.1 | R37.2 54.19,72.71 R38.1
N$75
  Top 0.254: IC8.2 R56.2 R52.2
N$76
  Top 0.254: C25.1 52.17,64.98 52.39,64.77 IC6.6 55.24,64.77 55.56,64.45 55.56,57.47 55.24,57.15 IC8.4
N$77
  Top 0.254: C30.1 64.03,59.69 R57.1
N$79
  Top 0.254: IC8.15 R57.2 R53.2
N$80
  Top 0.254: C26.1 60.54,64.98 60.33,64.77 IC6.9 57.78,64.77 57.47,64.45 57.47,57.47 57.78,57.15 IC8.13
N$81  (via drill 0.6)
  Top 0.254: IC6.8 60.33,63.5 60.54,63.28 C26.2 62.23,64.24 62.23,64.77 63.18,65.72 64.45,65.72 | v59.69,72.71 58.1,74.3 R35.2 | JP5.2 67.63,61.59 67.63,64.45 67.31,64.77 67.31,65.41 66.99,65.72 64.45,65.72 | 64.45,65.72 v64.45,71.44
  Bottom 0.254: v64.45,71.44 60.96,71.44 v59.69,72.71
N$82
  Top 0.254: R61.1 C33.1
N$83
  Top 0.254: IC8.7 R66.2 51.33,54.08 50.16,55.24 R61.2
N$84
  Top 0.254: R41.2 IC6.13 57.47,69.85 56.2,68.58 56.2,56.52 55.56,55.88 IC8.5
N$85
  Top 0.254: R41.1 R39.2
N$86
  Top 0.254: R38.2 58.1,72.71 59.12,71.69 IC6.14 60.33,71.12 60.64,71.44 R39.1 61.38,72.17 61.59,72.39 69.53,72.39 72.07,69.85 72.07,65.09 71.44,64.45 R55.1 | R67.1 67.63,53.02 70.17,55.56 70.17,58.1 70.48,58.42 70.48,60.96 70.7,61.17 R55.1 | R55.1 71.44,60.96
N$87  (via drill 0.6)
  Top 0.254: IC7.8 38.73,57.15 39.05,56.83 39.59,56.83 C32.1 R60.2 43.15,56.94 D9.C v43.18,55.24 | IC8.6 52.39,54.61 v51.75,55.24
  Bottom 0.254: v43.18,55.24 v51.75,55.24
N$88
  Top 0.254: R60.1 C32.2 38.95,58.63 38.73,58.42 IC7.9 36.2,58.42 35.88,58.1 R63.2 34.92,55.78 | 34.92,55.78 R62.2 | 34.92,55.78 34.92,53.34 34.29,52.7 29.21,52.7 27.94,53.98 27.94,54.93 25.4,57.47 25.4,59.37 23.77,61 R42.P$1
N$89
  Top 0.254: R58.2 R59.1 30.9,58.63 31.11,58.42 IC7.6
N$90
  Top 0.254: R54.2 21.27,60.74 R42.P$2
N$91
  Top 0.254: IC10.6 31.11,34.61 30.9,34.82 R92.1 R91.2
N$92  (via drill 0.6)
  Top 0.254: R58.1 28.47,56.83 27.94,56.83 26.99,57.78 v26.99,58.42 | v10.48,58.1 10.79,58.42 10.79,70.8 J5.P3
  Bottom 0.254: v26.99,58.42 26.67,58.1 v10.48,58.1
N$93
  Top 0.254: R111.2 66.67,12.38 66.99,12.7 J14.P3
N$94
  Top 0.254: R115.1 C57.1
N$96
  Top 0.254: 30.8,6.67 IC14.3 27.94,6.67 27.73,6.88 R117.2 | 30.8,6.67 IC14.6 35.56,6.67 36.41,5.82 R115.2 | R118.1 30.16,3.81 30.8,4.45 30.8,6.67
N$97
  Top 0.254: 29.21,2.01 R121.1 29.53,2.12 | 29.53,2.12 29.53,1.59 29.21,1.27 25.72,1.27 24.45,2.54 24.45,7.3 25.08,7.94 IC14.2 | 29.53,2.12 29.63,2.22 31.11,2.22 31.85,2.96 R119.2
N$98
  Top 0.254: C55.1 R113.2 R114.1
N$99
  Top 0.254: R120.2 34.29,3.81 | 34.29,3.81 R119.1 | IC14.5 34.29,5.34 34.29,3.81
N$100
  Top 0.254: IC14.1 27.94,9.21 27.44,9.71 D13.A
N$101
  Top 0.254: IC14.7 33.02,7.94 32.2,8.75 D14.A
N$102
  Top 0.254: D13.C 30.48,10.93 30.48,11.43 31.11,12.06 35.24,12.06 | 35.24,12.06 38.73,12.06 39.69,11.11 47.94,11.11 50.48,8.57 R113.1 | D14.C 35.24,10.93 35.24,12.06
N$103
  Top 0.254: R112.1 58.42,9.53 57.47,8.57 LED1.A
N$104
  Top 0.254: R116.2 51.01,7.2 R114.2 51.12,6.88 51.12,6.35 51.6,5.86 Q1.B
OUTPUT  (via drill 0.6)
  Top 0.254: IC13.1 52.7,19.05 52.49,19.27 R107.2 51.02,19.27 50.8,19.05 v50.8,13.34 51.75,12.38 R111.1 | C57.2 38.52,5.71 39.37,5.71 39.69,6.03 39.69,9.21 40.64,10.16 v47.62,10.16
  Bottom 0.254: v47.62,10.16 v50.8,13.34
PLUS_BUS  (via drill 0.6)
  Top 0.254: v61.28,84.14 61.28,83.19 60.33,82.23 IC5.12 57.78,82.23 57.47,81.92 57.47,78.42 56.2,77.15 53.02,77.15 52.39,76.52 R33.2 | v71.75,83.19 71.75,81.6 70.48,80.33 70.48,73.34 73.34,70.48 73.34,57.78 v73.03,57.47 72.71,57.15 72.71,53.98 70.48,51.75 70.48,49.53 73.34,46.67 73.34,32.7 v73.03,32.38 72.39,31.75 72.39,29.53 70.48,27.62 70.48,25.72 73.34,22.86 73.34,17.78 72.07,16.51 62.23,16.51 62.07,16.35 60.48,16.35 | IC13.6 60.33,16.51 60.48,16.35 | 60.48,16.35 60.54,16.3 R110.1 | R55.2 71.44,58.42 71.12,58.1 v71.12,57.47 | v70.8,32.38 70.8,33.02 71.44,33.66 R88.2
  Bottom 0.254: v71.75,83.19 62.23,83.19 v61.28,84.14 | v73.03,57.47 v71.12,57.47 | v73.03,32.38 v70.8,32.38
VCC  (via drill 0.6)
  Top 0.254: v58.42,90.17 58.2,89.95 C9.1 58.42,88.69 58.42,88.27 59.12,87.57 IC5.16 | 59.37,20.85 C52.1 | C58.+ 60.33,8.26 60.86,8.79 R112.2 | IC8.16 59.05,61.02 59.05,61.59 v59.69,62.23 | v64.14,61.59 C31.1
  Top 0.305: v60.33,96.52 60.96,95.89 60.96,95.35 C5.1 IC3.8 | IC6.4 52.7,67.31 51.85,68.16 C21.1 | v49.85,68.26 51.02,68.26 51.12,68.16 C21.1 | C21.1 51.44,68.26 | v49.85,43.81 51.33,43.81 C36.1 51.85,43.71 52.7,42.86 IC9.4 | C42.1 60.33,37.47 v60.01,37.78 59.12,36.89 IC11.16 | v28.26,86.04 29.43,86.04 C12.1 30.27,85.94 31.11,85.09 IC4.4 | IC7.4 31.11,60.96 30.27,61.81 C27.1 29.43,61.91 v28.26,61.91 | v59.37,21.91 59.37,20.85 | IC13.8 59.16,19.09 C52.1 | 31.11,37.15 IC10.4 | C43.1 29.43,38.1 v28.26,38.1 | IC12.8 35.14,23.97 C50.1 35.88,25.4 v37.15,24.13 | IC14.8 35.56,9.21 35.88,8.89 36.73,8.89 C56.1 38,8.99 v38.1,8.89
  Top 0.406: v27.62,101.28 25.72,101.28 24.77,102.23 19.37,102.23 5.08,87.95 v5.08,86.04 v5.08,60.96 v5.08,35.56 v5.08,25.4 v5.08,10.48 | v27.62,101.28 48.58,101.28 52.07,97.79 56.83,97.79 57.15,98.11 57.15,99.06 D2.C 59.05,99.38 60.33,100.65 67.63,100.65 v72.39,95.89 v75.56,92.71 v75.56,70.48 v75.56,61.59 v75.56,45.4 v75.56,37.78 v75.56,21.59 75.56,16.83 69.22,10.48 67.31,10.48 66.36,9.53 R112.2 | 31.11,37.15 30.27,38 C43.1 | v27.62,101.28 R1.1 | 27.62,104.31 C1.+ v24.45,104.46
  Bottom 0.254: v58.42,90.17 60.96,92.71 v75.56,92.71 | v59.69,62.23 60.33,61.59 v64.14,61.59 v75.56,61.59 | v75.56,37.78 65.72,37.78 65.09,38.42 60.64,38.42 v60.01,37.78
  Bottom 0.305: v72.39,95.89 72.07,96.2 60.64,96.2 v60.33,96.52 | v49.85,68.26 51.75,70.17 75.25,70.17 v75.56,70.48 | v49.85,43.81 51.44,45.4 v75.56,45.4 | v5.08,86.04 v28.26,86.04 | v28.26,61.91 25.08,65.09 17.78,65.09 13.65,60.96 v5.08,60.96 | v59.37,21.91 59.69,21.59 v75.56,21.59 | v28.26,38.1 25.72,35.56 v5.08,35.56 | v5.08,25.4 22.86,25.4 23.18,25.08 36.2,25.08 v37.15,24.13 | v5.08,10.48 35.24,10.48 36.83,8.89 v38.1,8.89
  Bottom 0.406: v27.62,101.28 v24.45,104.46
VEE  (via drill 0.6)
  Top 0.254: C51.2 59.05,24.98 | v37.78,100.01 36.83,100.01 36.51,99.69 R2.1 | v28.57,16.83 28.89,16.83 29.63,17.57 C53.2
  Top 0.305: 53.66,91.38 IC3.4 53.6,90.64 | IC5.9 61.17,78.42 C20.2 61.38,78.42 v63.18,78.42 | IC6.11 60.33,67.31 61.17,68.16 C22.2 62.02,68.26 v63.18,68.26 | IC8.9 59.12,50.84 C35.2 59.05,50.7 58.95,50.8 58.42,50.8 v57.15,52.07 | IC9.11 60.33,42.86 61.17,43.71 C37.2 62.02,43.81 v63.18,43.81 | IC4.11 38.73,85.09 39.59,85.94 C13.2 40.42,86.04 v41.59,86.04 | 29.53,18.31 C53.2 29.79,18.57 IC12.4 | v3.17,19.05 v3.17,32.38 | v55.88,13.97 C54.2 53.91,14.24 IC13.4 | IC11.9 59.12,25.25 C51.2 60.01,25.08 v60.33,24.77 | 53.6,90.64 C8.2 | 53.6,90.64 54.07,90.17 v54.61,90.17 | 39.69,37.15 IC10.11 | v39.69,37.78 39.69,37.15 | C44.2 39.69,36.3 39.69,37.15 | 40.01,60.22 C28.2 39.79,60.96 | v39.69,61.59 39.79,61.59 39.79,60.96 | 39.79,60.96 IC7.11
  Top 0.406: v76.83,15.24 v76.83,23.81 v76.83,41.91 v76.83,53.02 v76.83,68.9 v76.83,78.42 v76.83,94.3 76.83,97.47 70.17,104.14 D1.A P1.1 67.94,105.22 67.94,106.05 67.31,106.68 49.53,106.68 45.4,102.55 38.73,102.55 | v3.17,32.38 v3.17,62.23 v3.17,87.95 18.41,103.19 25.08,103.19 25.72,102.55 v37.78,102.55 38.73,102.55 | C2.- 38.73,104.31 38.73,102.55
  Bottom 0.254: v37.78,102.55 v37.78,100.01
  Bottom 0.305: v76.83,78.42 v63.18,78.42 | v63.18,68.26 63.82,68.9 v76.83,68.9 | v57.15,52.07 58.1,53.02 v76.83,53.02 | v63.18,43.81 63.18,42.86 64.14,41.91 v76.83,41.91 | v41.59,86.04 32.38,86.04 31.43,87 27.3,87 26.99,86.68 6.35,86.68 5.08,87.95 v3.17,87.95 | v39.69,61.59 30.8,61.59 26.67,65.72 17.46,65.72 13.34,61.59 6.03,61.59 5.4,62.23 v3.17,62.23 | v76.83,23.81 61.28,23.81 v60.33,24.77 | v3.17,32.38 v27.3,32.38 32.7,37.78 v39.69,37.78 | v28.57,16.83 26.35,19.05 v3.17,19.05 | v55.88,13.97 57.15,15.24 v76.83,15.24 | v54.61,90.17 58.74,94.3 v76.83,94.3

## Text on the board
bPlace: stripe | Red | 0dB | -6dB | Pre-gain
tNames: Shelves | cc-by-sa Olivier Gillet, 2014. v0.5
bNames: +12V | GND | -12V | Shelves | cc-by-sa Olivier Gillet, 2014. v0.5 | GND | GND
